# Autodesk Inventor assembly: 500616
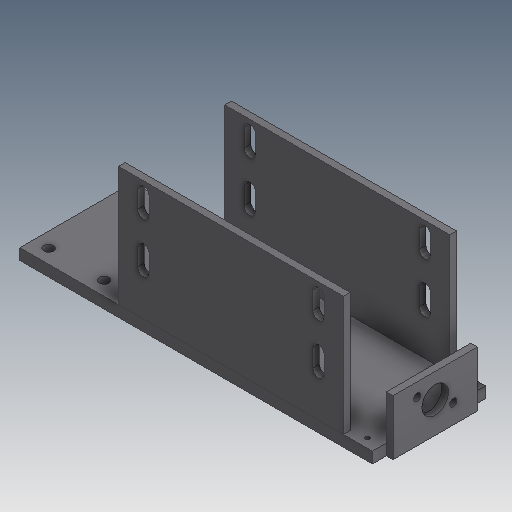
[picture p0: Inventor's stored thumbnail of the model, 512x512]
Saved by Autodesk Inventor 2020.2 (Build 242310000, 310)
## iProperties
Created: 2000-02
Part Number: 500616
Document SubType Name: Assembly
Description: WMT-CP,FH,CP,125,040,046,XX,X,CYL MOUNT FRAME, HOR ADJ.
Designer: sspink
Mass: 4655.99 g
Surface Area: 1771.44 cm^2
Volume: 592.365 cm^3
Density: 7.86 g/cm^3
Control State: 0
Checked Out: False
Master: False
Shininess: 0.0
Length Units: 11269
Angle Units: 11279
Time Units: 11290
Mass Units: 11283
Length Display Precision: 3
Angle Display Precision: 2
Compacted: True
Dimensions: 118x102x324 mm
Mass: 4,656 kg
DocNumber: 500616.iam
Folder: 01 - Themengebiete\Simplification\01 - Packaging machine\
VDS_Category: 3D Komponenten
Density: 0.0
Volumn: 0.0
Area: 0.0
PropertySet Name: Model Information
Author: sspink
Revision Number: -
Title: 500616
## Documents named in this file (4)
- D:\07 - DEMODATEN\OTX 2019 - Dataset - UPDATE - Dez2019\Designs\07-Packing machine\500616.iam
- D:\07 - DEMODATEN\OTX 2019 - Dataset - UPDATE - Dez2019\Designs\07-Packing machine\Parts\ADSK-011573.ipt
- D:\07 - DEMODATEN\OTX 2019 - Dataset - UPDATE - Dez2019\Designs\07-Packing machine\Parts\ADSK-011575.ipt
- D:\07 - DEMODATEN\OTX 2019 - Dataset - UPDATE - Dez2019\Designs\07-Packing machine\Parts\ADSK-011574.ipt
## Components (4 placed, 3 different names)
1. ADSK-011573:1 — Mate:1, Flush:1, Flush:2, Mate:2, Flush:3, Flush:4, Mate:3, Flush:5
2. ADSK-011574:1 — Mate:2, Flush:3, Flush:4, Flush:6
3. ADSK-011575:1 — Mate:1, Flush:1, Flush:2
4. ADSK-011574:2 — Mate:3, Flush:5, Flush:6
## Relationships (9: Flush 6, Mate 3)
- Mate:1: ADSK-011573:1 ↔ ADSK-011575:1
- Flush:1: ADSK-011573:1 ↔ ADSK-011575:1
- Flush:2: ADSK-011573:1 ↔ ADSK-011575:1
- Mate:2: ADSK-011573:1 ↔ ADSK-011574:1
- Flush:3: ADSK-011573:1 ↔ ADSK-011574:1
- Flush:4: ADSK-011573:1 ↔ ADSK-011574:1
- Mate:3: ADSK-011573:1 ↔ ADSK-011574:2
- Flush:5: ADSK-011573:1 ↔ ADSK-011574:2
- Flush:6: ADSK-011574:1 ↔ ADSK-011574:2
